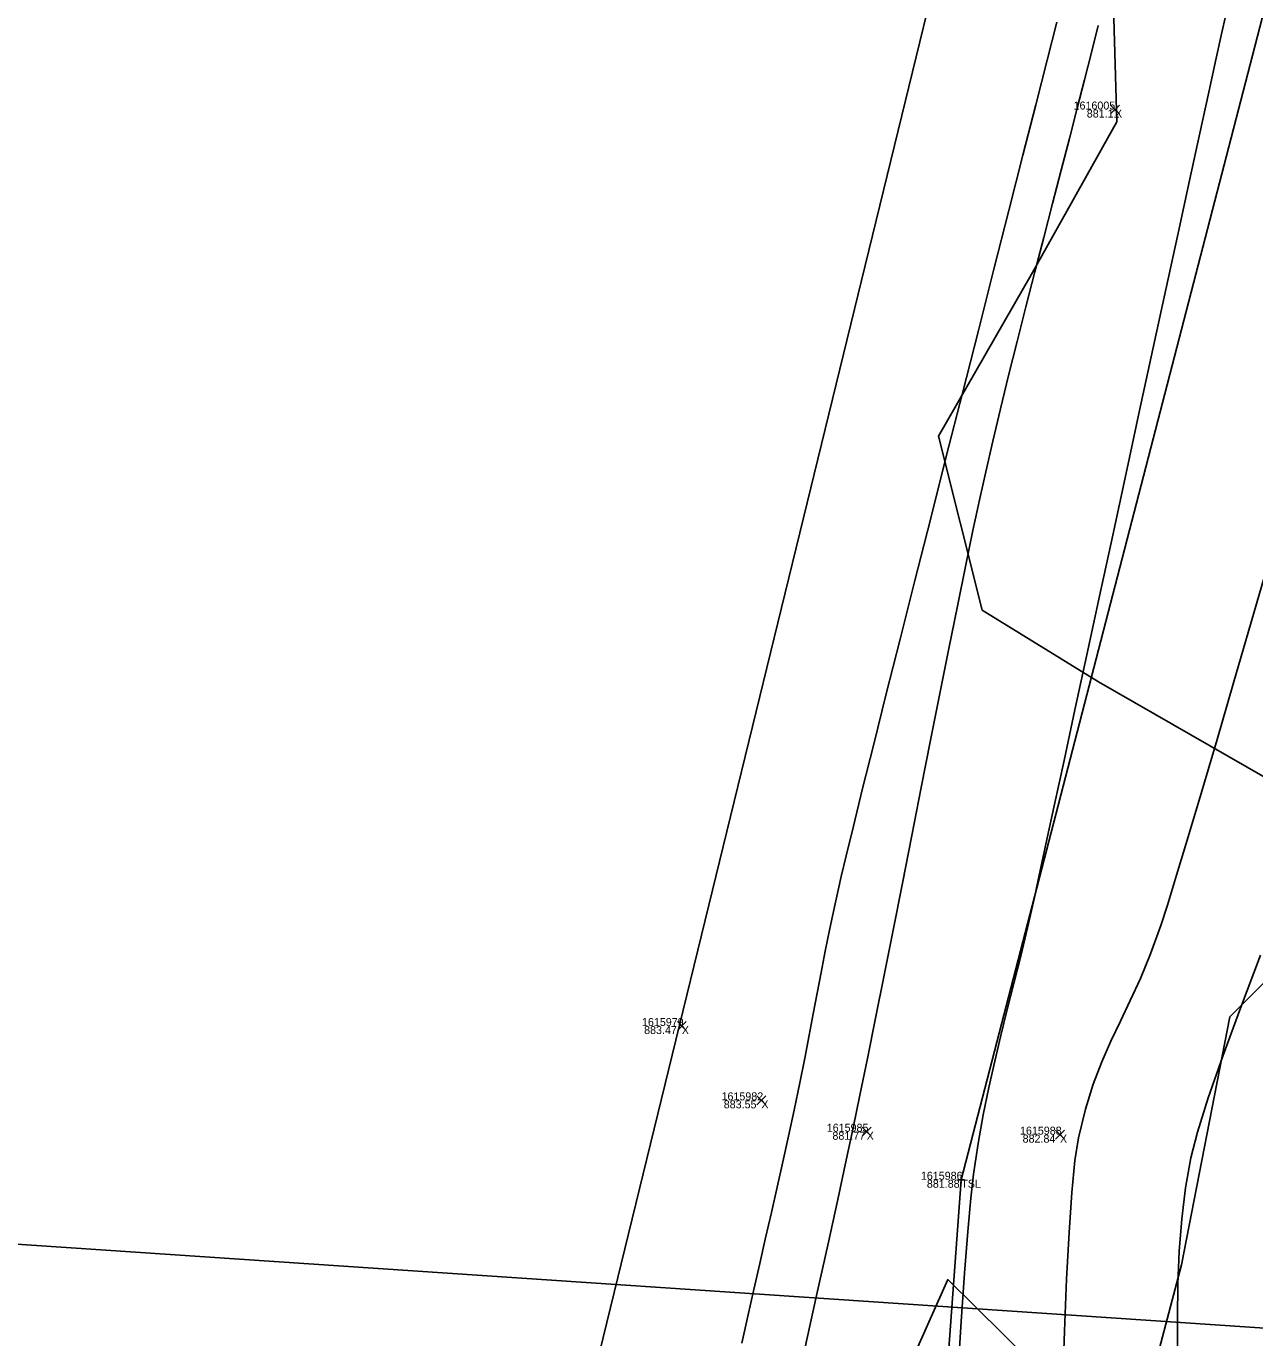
# Model space of a CAD drawing. Extents: x 1957117 to 1971063, y 701601 to 715861.
# Drawn here: x 1963081.5 to 1963135.2, y 705356 to 705413.3 of the extents above; entities that cross this region are included whole.
import ezdxf

# ---------------------------------------------------------------- set-up
doc = ezdxf.new("R2010")
doc.units = 0
for name, color, linetype in [('AP_X_Lights', 7, 'Continuous'), ('DT_X_Break_Line', 7, 'Continuous'), ('DT_X_Contour_Minor', 7, 'Continuous'), ('DT_X_TIN_Hull', 7, 'Continuous'), ('DV_X_Property_Line', 7, 'Continuous'), ('HY_X_Water_Edge', 7, 'Continuous'), ('PV_P_Drive', 7, 'Continuous'), ('PV_P_Shoulder', 7, 'Continuous'), ('RS_Raster1', 7, 'Continuous'), ('SC_Scratch1', 7, 'Continuous'), ('SC_Shading5', 7, 'Continuous'), ('VG_X_Tree_Line_Rt', 7, 'Continuous')]:
    doc.layers.add(name, color=color, linetype=linetype)

msp = doc.modelspace()

# ---------------------------------------------------------------- linework, layer by layer
at = {"layer": 'AP_X_Lights'}
for p, q in [((1963128.939, 705409.486), (1963129.327, 705409.876)), ((1963128.939, 705409.876), (1963129.327, 705409.486)), ((1963110, 705369.406), (1963110.388, 705369.796)), ((1963110, 705369.796), (1963110.388, 705369.406)), ((1963113.478, 705366.158), (1963113.866, 705366.548)), ((1963113.478, 705366.548), (1963113.866, 705366.158)), ((1963118.082, 705364.784), (1963118.47, 705365.174)), ((1963118.082, 705365.174), (1963118.47, 705364.784)), ((1963126.533, 705364.657), (1963126.921, 705365.047)), ((1963126.533, 705365.047), (1963126.921, 705364.657))]:
    msp.add_line(p, q, dxfattribs=at)
at = {"layer": 'DT_X_Break_Line'}
msp.add_lwpolyline([(1963059.618, 705072.384), (1963067.267, 705121.949), (1963084.435, 705172.155), (1963089.948, 705219.61), (1963104.733, 705267.194), (1963118.935, 705315.406), (1963122.413, 705362.88), (1963135.773, 705414.457), (1963142.701, 705466.671), (1963157.121, 705507.344), (1963171.033, 705561.75), (1963190.964, 705600.578), (1963199.065, 705656.682), (1963210.848, 705704.455), (1963218.329, 705756.178)], dxfattribs=at)
at = {"layer": 'DT_X_Contour_Minor'}
for points in [[(1963134.126, 705414.447), (1963133.812, 705413.047), (1963133.563, 705411.929), (1963133.237, 705410.447), (1963132.843, 705408.647), (1963132.391, 705406.576), (1963131.892, 705404.28), (1963131.356, 705401.807), (1963130.792, 705399.202), (1963130.21, 705396.513), (1963129.621, 705393.785), (1963129.034, 705391.067), (1963128.459, 705388.403), (1963127.906, 705385.842), (1963127.385, 705383.429), (1963126.907, 705381.211), (1963126.48, 705379.235), (1963126.115, 705377.548), (1963125.822, 705376.196), (1963125.611, 705375.225), (1963125.31, 705373.897), (1963125.011, 705372.651), (1963124.715, 705371.465), (1963124.426, 705370.319), (1963124.144, 705369.193), (1963123.874, 705368.065), (1963123.617, 705366.915), (1963123.375, 705365.722), (1963123.151, 705364.465), (1963122.947, 705363.124), (1963122.827, 705362.08), (1963122.696, 705360.62), (1963122.556, 705358.802), (1963122.409, 705356.681), (1963122.257, 705354.315)], [(1963134.126, 705414.447), (1963133.812, 705413.047), (1963133.563, 705411.929), (1963133.237, 705410.447), (1963132.843, 705408.647), (1963132.391, 705406.576), (1963131.892, 705404.28), (1963131.356, 705401.807), (1963130.792, 705399.202), (1963130.21, 705396.513), (1963129.621, 705393.785), (1963129.034, 705391.067), (1963128.459, 705388.403), (1963127.906, 705385.842), (1963127.385, 705383.429), (1963126.907, 705381.211), (1963126.48, 705379.235), (1963126.115, 705377.548), (1963125.822, 705376.196), (1963125.611, 705375.225), (1963125.31, 705373.897), (1963125.011, 705372.651), (1963124.715, 705371.465), (1963124.426, 705370.319), (1963124.144, 705369.193), (1963123.874, 705368.065), (1963123.617, 705366.915), (1963123.375, 705365.722), (1963123.151, 705364.465), (1963122.947, 705363.124), (1963122.827, 705362.08), (1963122.696, 705360.62), (1963122.556, 705358.802), (1963122.409, 705356.681), (1963122.257, 705354.315)], [(1963112.826, 705355.735), (1963113.086, 705356.921), (1963113.344, 705358.078), (1963113.601, 705359.214), (1963113.857, 705360.334), (1963114.11, 705361.446), (1963114.361, 705362.554), (1963114.611, 705363.666), (1963114.857, 705364.788), (1963115.102, 705365.926), (1963115.35, 705367.122), (1963115.567, 705368.203), (1963115.76, 705369.197), (1963115.938, 705370.132), (1963116.11, 705371.039), (1963116.283, 705371.945), (1963116.467, 705372.88), (1963116.67, 705373.871), (1963116.9, 705374.949), (1963117.165, 705376.141), (1963117.378, 705377.05), (1963117.694, 705378.348), (1963118.099, 705379.99), (1963118.583, 705381.93), (1963119.133, 705384.123), (1963119.737, 705386.522), (1963120.384, 705389.082), (1963121.062, 705391.757), (1963121.759, 705394.502), (1963122.462, 705397.272), (1963123.161, 705400.02), (1963123.843, 705402.701), (1963124.496, 705405.27), (1963125.109, 705407.68), (1963125.669, 705409.886), (1963126.165, 705411.843), (1963126.585, 705413.504)], [(1963112.826, 705355.735), (1963113.086, 705356.921), (1963113.344, 705358.078), (1963113.601, 705359.214), (1963113.857, 705360.334), (1963114.11, 705361.446), (1963114.361, 705362.554), (1963114.611, 705363.666), (1963114.857, 705364.788), (1963115.102, 705365.926), (1963115.35, 705367.122), (1963115.567, 705368.203), (1963115.76, 705369.197), (1963115.938, 705370.132), (1963116.11, 705371.039), (1963116.283, 705371.945), (1963116.467, 705372.88), (1963116.67, 705373.871), (1963116.9, 705374.949), (1963117.165, 705376.141), (1963117.378, 705377.05), (1963117.694, 705378.348), (1963118.099, 705379.99), (1963118.583, 705381.93), (1963119.133, 705384.123), (1963119.737, 705386.522), (1963120.384, 705389.082), (1963121.062, 705391.757), (1963121.759, 705394.502), (1963122.462, 705397.272), (1963123.161, 705400.02), (1963123.843, 705402.701), (1963124.496, 705405.27), (1963125.109, 705407.68), (1963125.669, 705409.886), (1963126.165, 705411.843), (1963126.585, 705413.504)], [(1963115.555, 705355.43), (1963116.084, 705357.815), (1963116.572, 705360.024), (1963117.009, 705362.015), (1963117.384, 705363.74), (1963117.687, 705365.155), (1963117.983, 705366.578), (1963118.311, 705368.182), (1963118.666, 705369.939), (1963119.041, 705371.82), (1963119.434, 705373.798), (1963119.838, 705375.844), (1963120.249, 705377.93), (1963120.663, 705380.028), (1963121.074, 705382.109), (1963121.478, 705384.145), (1963121.87, 705386.108), (1963122.245, 705387.97), (1963122.598, 705389.702), (1963122.925, 705391.277), (1963123.221, 705392.666), (1963123.48, 705393.84), (1963123.791, 705395.181), (1963124.127, 705396.588), (1963124.484, 705398.046), (1963124.856, 705399.541), (1963125.24, 705401.057), (1963125.629, 705402.578), (1963126.019, 705404.09), (1963126.404, 705405.577), (1963126.78, 705407.024), (1963127.141, 705408.417), (1963127.483, 705409.739), (1963127.8, 705410.975), (1963128.087, 705412.11), (1963128.399, 705413.356)], [(1963115.555, 705355.43), (1963116.084, 705357.815), (1963116.572, 705360.024), (1963117.009, 705362.015), (1963117.384, 705363.74), (1963117.687, 705365.155), (1963117.983, 705366.578), (1963118.311, 705368.182), (1963118.666, 705369.939), (1963119.041, 705371.82), (1963119.434, 705373.798), (1963119.838, 705375.844), (1963120.249, 705377.93), (1963120.663, 705380.028), (1963121.074, 705382.109), (1963121.478, 705384.145), (1963121.87, 705386.108), (1963122.245, 705387.97), (1963122.598, 705389.702), (1963122.925, 705391.277), (1963123.221, 705392.666), (1963123.48, 705393.84), (1963123.791, 705395.181), (1963124.127, 705396.588), (1963124.484, 705398.046), (1963124.856, 705399.541), (1963125.24, 705401.057), (1963125.629, 705402.578), (1963126.019, 705404.09), (1963126.404, 705405.577), (1963126.78, 705407.024), (1963127.141, 705408.417), (1963127.483, 705409.739), (1963127.8, 705410.975), (1963128.087, 705412.11), (1963128.399, 705413.356)], [(1963135.888, 705390.023), (1963135.09, 705387.26), (1963134.321, 705384.613), (1963133.596, 705382.132), (1963132.93, 705379.868), (1963132.336, 705377.872), (1963131.83, 705376.194), (1963131.427, 705374.884), (1963131.14, 705373.994), (1963130.692, 705372.76), (1963130.244, 705371.683), (1963129.801, 705370.719), (1963129.368, 705369.82), (1963128.951, 705368.941), (1963128.553, 705368.037), (1963128.181, 705367.061), (1963127.839, 705365.967), (1963127.533, 705364.71), (1963127.381, 705363.724), (1963127.246, 705362.327), (1963127.127, 705360.579), (1963127.021, 705358.535), (1963126.926, 705356.256), (1963126.839, 705353.797)], [(1963135.888, 705390.023), (1963135.09, 705387.26), (1963134.321, 705384.613), (1963133.596, 705382.132), (1963132.93, 705379.868), (1963132.336, 705377.872), (1963131.83, 705376.194), (1963131.427, 705374.884), (1963131.14, 705373.994), (1963130.692, 705372.76), (1963130.244, 705371.683), (1963129.801, 705370.719), (1963129.368, 705369.82), (1963128.951, 705368.941), (1963128.553, 705368.037), (1963128.181, 705367.061), (1963127.839, 705365.967), (1963127.533, 705364.71), (1963127.381, 705363.724), (1963127.246, 705362.327), (1963127.127, 705360.579), (1963127.021, 705358.535), (1963126.926, 705356.256), (1963126.839, 705353.797)], [(1963135.501, 705372.697), (1963134.618, 705370.377), (1963133.848, 705368.284), (1963133.214, 705366.465), (1963132.739, 705364.968), (1963132.445, 705363.842), (1963132.212, 705362.532), (1963132.05, 705361.167), (1963131.945, 705359.758), (1963131.888, 705358.314), (1963131.865, 705356.843), (1963131.867, 705355.357)], [(1963135.501, 705372.697), (1963134.618, 705370.377), (1963133.848, 705368.284), (1963133.214, 705366.465), (1963132.739, 705364.968), (1963132.445, 705363.842), (1963132.212, 705362.532), (1963132.05, 705361.167), (1963131.945, 705359.758), (1963131.888, 705358.314), (1963131.865, 705356.843), (1963131.867, 705355.357)]]:
    msp.add_lwpolyline(points, dxfattribs=at)
at = {"layer": 'DT_X_TIN_Hull'}
msp.add_lwpolyline([(1963254.734, 705951.873), (1963238.207, 705904.757), (1963226.355, 705855.27), (1963191.43, 705709.793), (1963179.827, 705661.653), (1963168.092, 705612.411), (1963156.438, 705563.606), (1963144.855, 705514.97), (1963136.901, 705465.31), (1963121.943, 705418.117), (1963098.235, 705321.162), (1963062.2, 705175.46), (1963037.999, 705077.244)], dxfattribs=at)
at = {"layer": 'DV_X_Property_Line'}
msp.add_line((1963140.095, 705356.086), (1959478.471, 705602.861), dxfattribs=at)
at = {"layer": 'HY_X_Water_Edge'}
msp.add_spline([(1963191.723, 701994.048), (1963062.047, 702441.167), (1962863.491, 703169.356), (1962827.53, 703438.691), (1962823.213, 703537.412), (1962817.962, 703593.874), (1962817.97, 703697.316), (1962828.582, 703804.235), (1962836.461, 703844.734), (1962850.687, 703896.004), (1962867.251, 703938.846), (1962873.848, 703992.355), (1962884.135, 704091.371), (1962891.241, 704140.854), (1962897.382, 704180.529), (1962905.467, 704230.979), (1962943.949, 704328.022), (1962948.537, 704378.842), (1962964.114, 704426.264), (1963004.885, 704570.73), (1963042.054, 704716.522), (1963062.038, 704814.417), (1963072.171, 704860.237), (1963090.023, 704956.798), (1963107.066, 705031.783), (1963133.773, 705105.742), (1963148.685, 705206.74), (1963175.48, 705301.059), (1963191.635, 705353.417), (1963210.988, 705447.286), (1963219.532, 705497.27), (1963230.124, 705549.475), (1963251.052, 705591.159), (1963275.289, 705693.429), (1963292.982, 705784.032), (1963302.841, 705839.645), (1963335.126, 705936.766), (1963359.752, 706046.75), (1963389.133, 706177.299), (1963417.827, 706273.456), (1963475.868, 706451.902), (1963533.782, 706640.53), (1963553.86, 706696.984), (1963580.184, 706715.425), (1963609.172, 706718.73), (1963617.062, 706714.691), (1963619.447, 706694.678), (1963564.282, 706533.07), (1963531.853, 706395.229), (1963434.4, 706006.96), (1963354.09, 705679.186), (1963237.513, 705206.07), (1963167.369, 704892.962), (1963059.145, 704434.176), (1962907.914, 703908.742), (1962877.458, 703703.326), (1962898.357, 703412.121), (1962942.65, 703052.267), (1963048.963, 702674.866), (1963191.468, 702189.666), (1963245.396, 702019.832)], degree=3, dxfattribs=at)
at = {"layer": 'PV_P_Drive'}
for p, q in [((1963122.267, 705362.88), (1963122.559, 705362.88)), ((1963122.413, 705363.026), (1963122.413, 705362.734)), ((1963122.413, 705362.88), (1963122.413, 705362.88))]:
    msp.add_line(p, q, dxfattribs=at)
at = {"layer": 'SC_Shading5'}
for points in [[(1963026.912, 704294.121), (1963138.818, 704737.794), (1963251.679, 705213.963), (1963374.306, 705730.111), (1963454.783, 706045.593), (1963517.244, 706296.713), (1963562.763, 706479.256), (1963580.13, 706553.799), (1963589.678, 706586.994)], [(1963609.915, 706579.703), (1963587.283, 706499.153), (1963552.056, 706354.005), (1963480.911, 706069.234), (1963357.401, 705576.869), (1963272.751, 705226.931), (1963210.247, 704956.481), (1963044.97, 704288.881)]]:
    msp.add_spline(points, degree=3, dxfattribs=at)
at = {"layer": 'VG_X_Tree_Line_Rt'}
for points in [[(1963128.863, 705421.23), (1963129.219, 705409.143), (1963125.525, 705402.55), (1963121.412, 705395.402), (1963123.33, 705387.792), (1963128.412, 705384.652), (1963135.696, 705380.476), (1963139.494, 705375.341), (1963134.15, 705370.002), (1963132.038, 705359.161), (1963129.619, 705349.992)], [(1963127.904, 705352.518), (1963121.821, 705358.514), (1963118.017, 705349.97)]]:
    msp.add_lwpolyline(points, dxfattribs=at)

# ---------------------------------------------------------------- texts
at = {"layer": 'PV_P_Shoulder'}
for s, p in [('881.11', (1963127.901, 705409.331)), ('883.47', (1963108.546, 705369.251)), ('883.55', (1963112.027, 705366.003)), ('881.77', (1963116.78, 705364.629)), ('882.84', (1963125.096, 705364.502)), ('881.88', (1963120.909, 705362.53))]:
    msp.add_text(s, height=0.35, dxfattribs=at).set_placement(p)
at = {"layer": 'RS_Raster1'}
for s, p in [('1616005', (1963127.323, 705409.681)), ('1615979', (1963108.453, 705369.601)), ('1615982', (1963111.931, 705366.353)), ('1615985', (1963116.532, 705364.979)), ('1615988', (1963124.98, 705364.852)), ('1615986', (1963120.647, 705362.88))]:
    msp.add_text(s, height=0.35, dxfattribs=at).set_placement(p)
at = {"layer": 'SC_Scratch1'}
for s, p in [('X', (1963129.133, 705409.331)), ('X', (1963110.194, 705369.251)), ('X', (1963113.672, 705366.003)), ('X', (1963118.276, 705364.629)), ('X', (1963126.727, 705364.502)), ('TSL', (1963122.413, 705362.53))]:
    msp.add_text(s, height=0.35, dxfattribs=at).set_placement(p)

doc.saveas('drawing.dxf')
